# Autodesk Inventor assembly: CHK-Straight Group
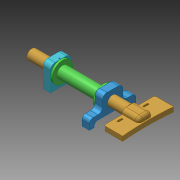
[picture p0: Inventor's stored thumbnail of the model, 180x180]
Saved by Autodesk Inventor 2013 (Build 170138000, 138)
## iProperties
Created: 2013-03
Part Number: CHK-Straight Group
Document SubType Name: Assembly
Designer: rYan
Author: rYan
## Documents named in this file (3)
- E:\Tigers SVN\mechanik\2013\Inventor\Checks\CHK-Straight Group.iam
- E:\Tigers SVN\mechanik\2013\Inventor\Kicker\UBG-Spulen.iam
- E:\Tigers SVN\mechanik\2013\Inventor\Checks\CHK-Straight Kicker.iam
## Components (2 placed, 2 different names)
1. UBG-Spulen:1 [sub-assembly] — Mate:1, Angle:1
2. CHK-Straight Kicker:1 [sub-assembly] — Mate:1, Angle:1
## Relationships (2: Mate 1, Angle 1)
- Mate:1: UBG-Spulen:1 ↔ CHK-Straight Kicker:1
- Angle:1: UBG-Spulen:1 ↔ CHK-Straight Kicker:1
